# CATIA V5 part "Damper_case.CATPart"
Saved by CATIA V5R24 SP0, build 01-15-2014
Part number: Damper_case
Bounding box of the stored display mesh (mm): x -11 to 11, y -5 to 56, z -10.875 to 10.875
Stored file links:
  \\cdl-main\FTPSERVER\Minsik\2016\2\Damper_case.CATPart
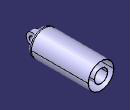
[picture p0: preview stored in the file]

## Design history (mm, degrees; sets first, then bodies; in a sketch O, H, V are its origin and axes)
Set1
  Sketch1 on yz-plane, origin (0, 0, 0), H (0, 1, 0), V (0, 0, 1)
    circle A1 centre (0, 0) radius 5
    point P1 (5, 0)
    circle A2 centre (0, 0) radius 2.5
    radius A2 = 2.5
    radius A1 = 5
    coincidence: A1 P1, P1 H
Body1 (main body)
  Pad1: profile Sketch1, direction (1, 0, 0), length 2.5, mirrored extent
  Sketch2 on yz-plane, origin (0, 0, 0), H (0, 1, 0), V (0, 0, 1)
    axis line L1 (21.7544, 0) -> (-14.1544, 0)
    point P1 (21.7544, 0)
    point P3 (5, 0)
    line L2 (5, 0) -> (5, 9)
    line L3 (7, 11) -> (8, 11)
    line L4 (8, 11) -> (8, 0)
    point P5 (8, 0)
    reference projected circle E1 centre (0, 0) radius 5 from edge [face of Pad1 from Sketch1.A1 | end face of Pad1]
    arc A1 centre (7, 9) radius 2 from (5, 9) to (7, 11) cw
    distance L4 L2 = 3
    distance L3 H = 11
    radius A1 = 2
    coincidence: P1 H, P3 L1, P5 L1
    vertical: L2 V, L4 V
    horizontal: L3 H
    tangency: L2 E1, A1 L2, A1 L3
  Shaft1: profile Sketch2, axis Sketch2.L1, angle 360
  Sketch3 on face of Shaft1 from Sketch2.L4, origin (0, 8, 0), H (-1, 0, 0), V (0, 0, 1)
    circle A1 centre (0, 0) radius 11
    radius A1 = 11
  Pad2: profile Sketch3, direction (0, 1, 0), length 48, thin wall 0.3
  Sketch4 on face of Shaft1 from Sketch2.L4, origin (0, 8, 0), H (-1, 0, 0), V (0, 0, 1)
    circle A1 centre (0, 0) radius 5.5
    radius A1 = 5.5
  Pad3: profile Sketch4, direction (0, 1, 0), length 48, thin wall 0, second thickness 0.3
